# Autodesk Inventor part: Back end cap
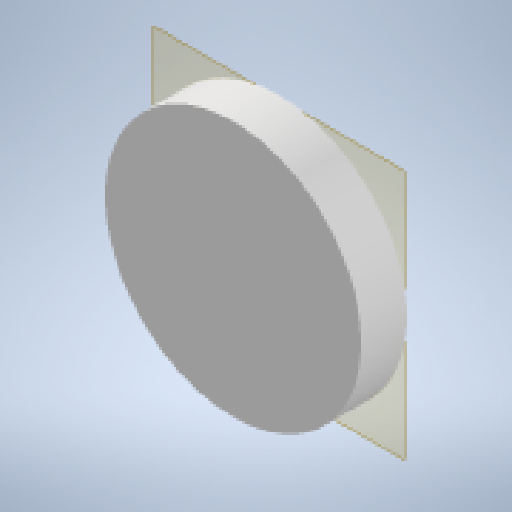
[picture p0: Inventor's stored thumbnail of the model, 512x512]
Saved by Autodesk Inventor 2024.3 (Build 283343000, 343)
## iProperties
Created: 2024-12
Part Number: Back end cap
Material: Generic
Document SubType Name: Modeling
Designer: ruhr
Density: 1 g/cm^3
Appearance: Default
Author: ruhr
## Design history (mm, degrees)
workplane "Work Plane1"
sketch "Sketch1"
  geometry: C1 r 22.5 at (0, 0); 1 further point
  constraints: 1 centre point, 1 coincident
  dimensions: "d0" = 45 diameter of C1
extrude "Extrusion1" new body sketch "Sketch1" distance "d1" = 8; taper "d2" = 0 deg
body "Solid1"
